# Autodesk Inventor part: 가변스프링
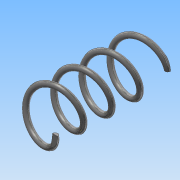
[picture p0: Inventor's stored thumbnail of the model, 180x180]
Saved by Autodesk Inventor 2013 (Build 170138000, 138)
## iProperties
Created: 2015-09
Part Number: 가변스프링
Material: 강철, 탄소
Document SubType Name: Modeling
Designer: Administrator
Mass: 4.92088 g
Surface Area: 12.7468 cm^2
Volume: 0.625271 cm^3
Density: 7.87 g/cm^3
Author: Administrator
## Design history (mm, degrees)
sketch "스케치1"
  geometry: L1 (0, 0)-(0, 42); L2 (0, 0)-(8, 0); L3 (0, 42)-(8, 42); C1 r 1 at (8, 0)
  constraints: 6 end point, 1 centre point, 1 horizontal alignment, 1 parallel, 1 perpendicular, 1 vertical
  dimensions: "d0" = 42 distance of L1.start L1.end (derived); "d1" = 2 diameter of C1; "d2" = 16 diameter of L2.end L1; "d3" = 8 distance of L1.end L3.end
feature "코일1" pitch "d4" = 10; turns "d6" = 4; dims "d5" = 42 (= d0), "d7" = 0, angle "d8" = 90 deg, angle "d9" = 90 deg, "d10" = 0, "d11" = 0
sketch "스케치2"
  geometry: L1 (42, 10)-(0, 10); L2 (0, 10)-(0, -10); L3 (0, -10)-(42, -10); L4 (42, -10)-(42, 10); 2 further points
  constraints: 8 end point, 2 parallel, 1 coincident, 1 horizontal, 1 midpoint, 1 perpendicular
  dimensions: "d12" = 20 distance of L3.end L1.start; "d14" = 42 distance of L2.end L3.end (derived)
extrude "돌출1" sketch "스케치2" stored distance "d15" = 10; taper "d16" = 0 deg
node "솔리드1"
